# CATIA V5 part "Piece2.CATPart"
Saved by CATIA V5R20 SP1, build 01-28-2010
Part number: Piece2
Bounding box of the stored display mesh (mm): x 59.363 to 100.369, y 146.602 to 196.993, z -385.882 to -237.501
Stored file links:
  C:\Users\RENARD Simon\Documents\Cours IFMA\2ème année\IAO\Piece2.CATPart
  C:\Users\RENARD Simon\Documents\Cours IFMA\2ème année\IAO\Trainattero.CATProduct
  C:\Users\RENARD Simon\Documents\Cours IFMA\2ème année\IAO\Sqpiece2.CATPart
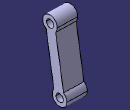
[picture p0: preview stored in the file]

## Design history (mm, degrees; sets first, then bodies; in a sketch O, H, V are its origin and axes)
Set1
  Plane1: linked copy from another document
  Line1: linked copy from another document
  Line2: linked copy from another document
Body1 (main body)
  Sketch1 on Plane1, origin (76.3156, -1.5629, 0), H (0.0205, 0.9998, 0), V (0, 0, 1)
    arc A1 centre (163.5883, -252.4969) radius 15 from (178.5883, -252.4969) to (155.5487, -265.1604) ccw
    point P1 (163.5883, -252.4969)
    arc A2 centre (183.1883, -370.8854) radius 15 from (198.1883, -370.8854) to (191.2279, -358.2219) ccw
    point P2 (183.1883, -370.8854)
    reference projected point E1 (183.1883, -370.8854) from Line2
    reference projected point E2 (163.5883, -252.4969) from Line1
    line L1 (175.2802, -261.8938) -> (191.2279, -358.2219)
    point P3 (175.2802, -261.8938)
    line L2 (155.5487, -265.1604) -> (171.4964, -361.4885)
    point P5 (155.5487, -265.1604)
    point P6 (171.4964, -361.4885)
    reference projected point E3 (183.1883, -370.8854) from Line2
    arc A3 centre (183.1883, -370.8854) radius 15 from (171.4964, -361.4885) to (198.1883, -370.8854) ccw
    point P7 (198.1883, -370.8854)
    point P8 (198.1883, -370.8854)
    arc A4 centre (163.5883, -252.4969) radius 15 from (175.2802, -261.8938) to (178.5883, -252.4969) ccw
    point P9 (178.5883, -252.4969)
    point P10 (178.5883, -252.4969)
    reference projected point E4 (163.5883, -252.4969) from Line1
    radius A1 = 15
    radius A2 = 15
    distance L1 L2 = 20
    distance E3 L2 = 10
    distance L1 E4 = 10
    coincidence: P2 E1, P1 E2, P3 A1, P5 A1, P6 A2, A2 A3, A1 A4, P7 P8, P9 P10
    parallelism: L1 L2
  Pad1: profile Sketch1, direction (0.9998, -0.0205, 0), length 20, mirrored extent
  Sketch2 on start face of Pad1, origin (56.3198, -1.1534, 0), H (-0.0205, -0.9998, 0), V (0, 0, 1)
    circle A1 centre (-163.5883, -252.4969) radius 7.5
    point P1 (-163.5883, -252.4969)
    circle A2 centre (-183.1883, -370.8854) radius 7.5
    point P2 (-183.1883, -370.8854)
    reference projected point E1 (-183.1883, -370.8854) from Line2
    reference projected point E2 (-163.5883, -252.4969) from Line1
    radius A2 = 7.5
    radius A1 = 7.5
    coincidence: P2 E1, P1 E2
  Pocket1: profile Sketch2, direction (0.9998, -0.0205, 0), length 40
